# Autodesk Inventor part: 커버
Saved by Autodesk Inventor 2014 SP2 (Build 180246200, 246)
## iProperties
Created: 2024-04
Part Number: 커버
Material: Generic
Document SubType Name: Modeling
Designer: Administrator
Density: 1 g/cm^3
Appearance: Default
Author: Administrator
Author: jhkim
Creation Date: 2024-04-08
Sending System: Autodesk Inventor 2025
Preprocessor: ST-DEVELOPER v20
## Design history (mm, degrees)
node "커버1"
node "솔리드1"
node "기준1"
